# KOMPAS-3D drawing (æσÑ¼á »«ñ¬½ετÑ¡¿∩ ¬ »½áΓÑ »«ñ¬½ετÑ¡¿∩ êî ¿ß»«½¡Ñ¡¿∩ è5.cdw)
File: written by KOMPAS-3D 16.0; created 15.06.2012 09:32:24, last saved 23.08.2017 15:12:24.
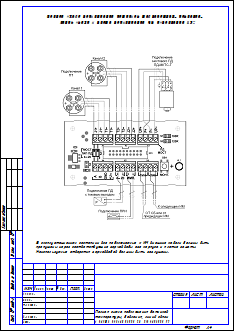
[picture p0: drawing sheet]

Sheet 1: A4, portrait

Title block, sheet 1: name: г. Москва, ул. Нежинская, д. 14, к.8 (кв. 1 и кв. 2); sheets: 32; sheet format: A4; stored path: W:\Users\chesnokov\Desktop\Новая папка\5 тр LTKR.cdw

Views: Вид 2, Вид 3, Вид 4, Вид 5
Referenced files in C:\Users\chesnokov\Desktop\Общее для проектов\заготовки для проектирования\Картинки\: Подключение К5.png
Referenced files in C:\Program Files (x86)\ASCON\KOMPAS-3D V16\Sys\: spds.lcs, EngSys.lcs, GRAPHIC.LHS
Referenced files: graphic.tdp
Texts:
  МО, Клинский район, д. Решетниково, ул. Центральная, д.14
  GOST Common
  Normal
  List Paragraph
  heading 3
  для схемы
  txt
  краны
  Фоновая заливка
  Т0-элементы
  В эксплуатационном состоянии все подключаемые к ИМ внешние кабели должны быть
  пропущены через соответствующие гермовводы его корпуса и плотно зажаты.
  Неиспользуемые отверстия гермовводов должны быть заглушены.
  Полная схема подключения датчиков температуры, давления,
  линий связи к плате подключения ИМ исполнения К5:
  Размеры, параметризация
  сит. план
  подача ГВС
  обратка ГВС
  хвс
  обратка
  POLYLINE_STYLE_0.25_RGB_0_0_0
  стены
  Основная (не является границей для штриховки)
  POLYLINE_STYLE_0.18_RGB_0_0_0
  ХВС
  зеленая
  Красная тонкая
  арматура
  Подача
  Скрытая линия
  Ось Z
  Ось Y
  Ось X
  Образующая трубопровода (проектируемого)
  Трубопровод толщиной 0.6мм (одна линия)
  Трубопровод толщиной 1.2мм (одна линия)
  Трубопровод толщиной 1.0мм (одна линия)
  Трубопровод толщиной 0.8мм (одна линия)
  Трубопровод существующий (одна линия)
  Трубопровод невидимый (одна линия)
  Трубопровод демонтируемый (одна линия)
  Осевая трубопровода
  Осевая трубопровода (демонтируемого)
  Образующая трубопровода (существующего)
  Образующая трубопровода (невидимого)
  Изолированный трубопровод проектируемый (одна линия)
  Изолированный трубопровод существующий (одна линия)
  Образующая изоляции
  Изоляция
  Изолированный трубопровод невидимый (одна линия)
  Штрих пвс 075
  штрих пвс 2,5
  существующее оборудование
  Существующее оборудование
  K5LT_BASIC_RGB_0_0_255_THICK_0.53
  POLYLINE_STYLE_1.51_RGB_0_0_255
  POLYLINE_STYLE_0.50_RGB_128_128_128
  K5LT_AXLED_RGB_255_128_0_SC_1_THICK_0.18
  ACAD_ISO04W100_RGB_0_0_0_SC_1_THICK_0.18
  тонкая черная
  пломбировка
  Провода
  синий штрих
  Стили документа
  G2co
  расход вторичной воды объемный
  расход вторичной воды объемный при 70гр
  Gco
  расход теплоносителя массовый
  расход теплоносит объемн подающ
  расход теплоносит объемн обр
  Лапир
  Ghvs
  Im1
  Im2
  Im3
  Im4
  Im5
  Khvs
  норматив ХВС
  число подъездов
  число этажей
  Nkv
  число квартир
  тепловая нагрузка на отопление
  сумма Q
  Qgvs
  тепловая нагрузка ГВС
  тепловая нагрузка на циркуляцию ГВС
  иммитовставка или под манометр
  ro1
  ro2
  ro3
  ro4
  верх предел темп граф
  нижн предел темп граф
  темп подачи ГВС
  темп обр ГВС
  темр хол воды
  vzdh
  Kchn
  Ktp
  Knp
  beta
  tnv
  Vклап
  KLP
  RPD
  RDS
  PUMP
  ro5
  Переход К-76 x 3-38 x 2-09Г2С ГОСТ 17378-2001
  Переход ГОСТ 17378-2001
  Переход
  ГОСТ
  Сталь 09Г2С ГОСТ 19281-89
  Переход К-76 x 3-45 x 2,5-09Г2С ГОСТ 17378-2001
  Переход К-57 x 3-38 x 2-09Г2С ГОСТ 17378-2001
  Переход К-57 x 3-32 x 2-09Г2С ГОСТ 17378-2001
  Втулка 20x50
  Переход К-108 x 4-57 x 3-09Г2С ГОСТ 17378-2001
  Переход К-45 x 2,5-32 x 2-09Г2С ГОСТ 17378-2001
  Переход К-89 x 3,5-45 x 2,5-09Г2С ГОСТ 17378-2001
  Переход К-133 x 5-108 x 4-09Г2С ГОСТ 17378-2001
  Переход К-159 x 4,5-89 x 3,5-09Г2С ГОСТ 17378-2001
  Переход К-45 x 2,5-38 x 2-09Г2С ГОСТ 17378-2001
  Фланец 1-32-1 Ст3сп ГОСТ 12820-80
  Фланцы
  Фланец
  квадратный
  Ст3сп
  Ст3сп ГОСТ 380-2005
  Переход К-57 x 3-45 x 2,5-09Г2С ГОСТ 17378-2001
  Переход К-76 x 3-57 x 3-09Г2С ГОСТ 17378-2001
  Фланец 1-50-16 Ст3сп ГОСТ 12821-80
  Переход К-89 x 3,5-76 x 3,5-09Г2С ГОСТ 17378-2001
  Переход К-108 x 4-89 x 3,5-09Г2С ГОСТ 17378-2001
  Тройник 159 x 4,5-09Г2С ГОСТ 17376-2001
  Тройники ГОСТ 17376-2001
  Тройник
  Отвод 90-159 x 4-09Г2С ГОСТ 17375-2001
  Отвод ГОСТ 17375-2001
  Отвод
  Переход К-108 x 4-76 x 3,5-09Г2С ГОСТ 17378-2001
  Переход К-159 x 4,5-108 x 4-09Г2С ГОСТ 17378-2001
  Переход К-133 x 5-76 x 3,5-09Г2С ГОСТ 17378-2001
  Переход К-133 x 4-89 x 3,5-09Г2С ГОСТ 17378-2001
  Переход К-1-42,4 x 2,6-21,3 x 2-TS10 ГОСТ 17378-2001
  TS10
  Сталь TS10 ИСО 2604/2-75
  Фланец 1-20-16 Ст3сп ГОСТ 12820-80
  Лит-Масса-Масштаб
  Материал-Предприятие
  Title Specification
  Body Specification ( left align )
  Body Specificaton ( centered )
  Поз.
  Кол.
  Приме-
  чание
  Таблица спецификации
  Засыпка
  Штрих3
  Штрих2
  Штрих1
  Песок
  Штр0.5пр7
  Штр0.5пр12
  Штр0.3пр10
  Штр1.4пр21.21
  Штр1пр15
  Штр2.12пр35
  Штр1.5пр25
  Штр2.82пр42.42
  Штр2пр30
  SACNCR_ISO 1
  Электрощитовая
  Пр-1
  Ок-1
  вапвыапвы
  Обозначение стандарта
  Типоразмер
  Разраб.
  Пров.
  Т.контр.
  Н.контр.
  Утв.
  Полная схема подключения датчиков
  температуры, давления, линий связи
  к плате подключения ИМ исполнения К5
  Рабочие чертежи основного комплекта. ГОСТ Р 21.1101-2009 Ф3
  Стадия
  Лист
  Листов
  Изм.
  Кол.уч.
  №док.
  Подп.
  Дата
  Изменение
  Номер документа
  Подпись
  Наименование объекта строительства, в состав которого входит здание, наим. микр
  Наименование здания (сооружения)
  Порядковый номер листа
  Количество листов в документе
  Наименование изображения
  Индекс предприятия, выпускающего документ
  Инв. № подл.
  Подп. и дата
  Взам. инв. №
  Инвентарный номер подлинника
  Подпись принявшего подлинник на хранение
  Инвентарный номер подлинника, взамен которого выпущен данный подлинник
  Согласовано
  Формат листа
  Согласование
  03 Рабочие чертежи основного комплекта. ГОСТ Р 21.1101-2009 Ф3
Dimensions and other numbers on the sheet: 0; 1; 09Г2С; 2; 3; 4; 6; 8; 12; 16; 17; 19; 20; 21; 22; 23; 24; 25; 26; 30; 31; 33; 34; 52; 64; 65; 66; 67; 69; 70; 71; 72; 73; 74; 75; 5; 32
